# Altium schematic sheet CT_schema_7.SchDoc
size 405 x 379 mm
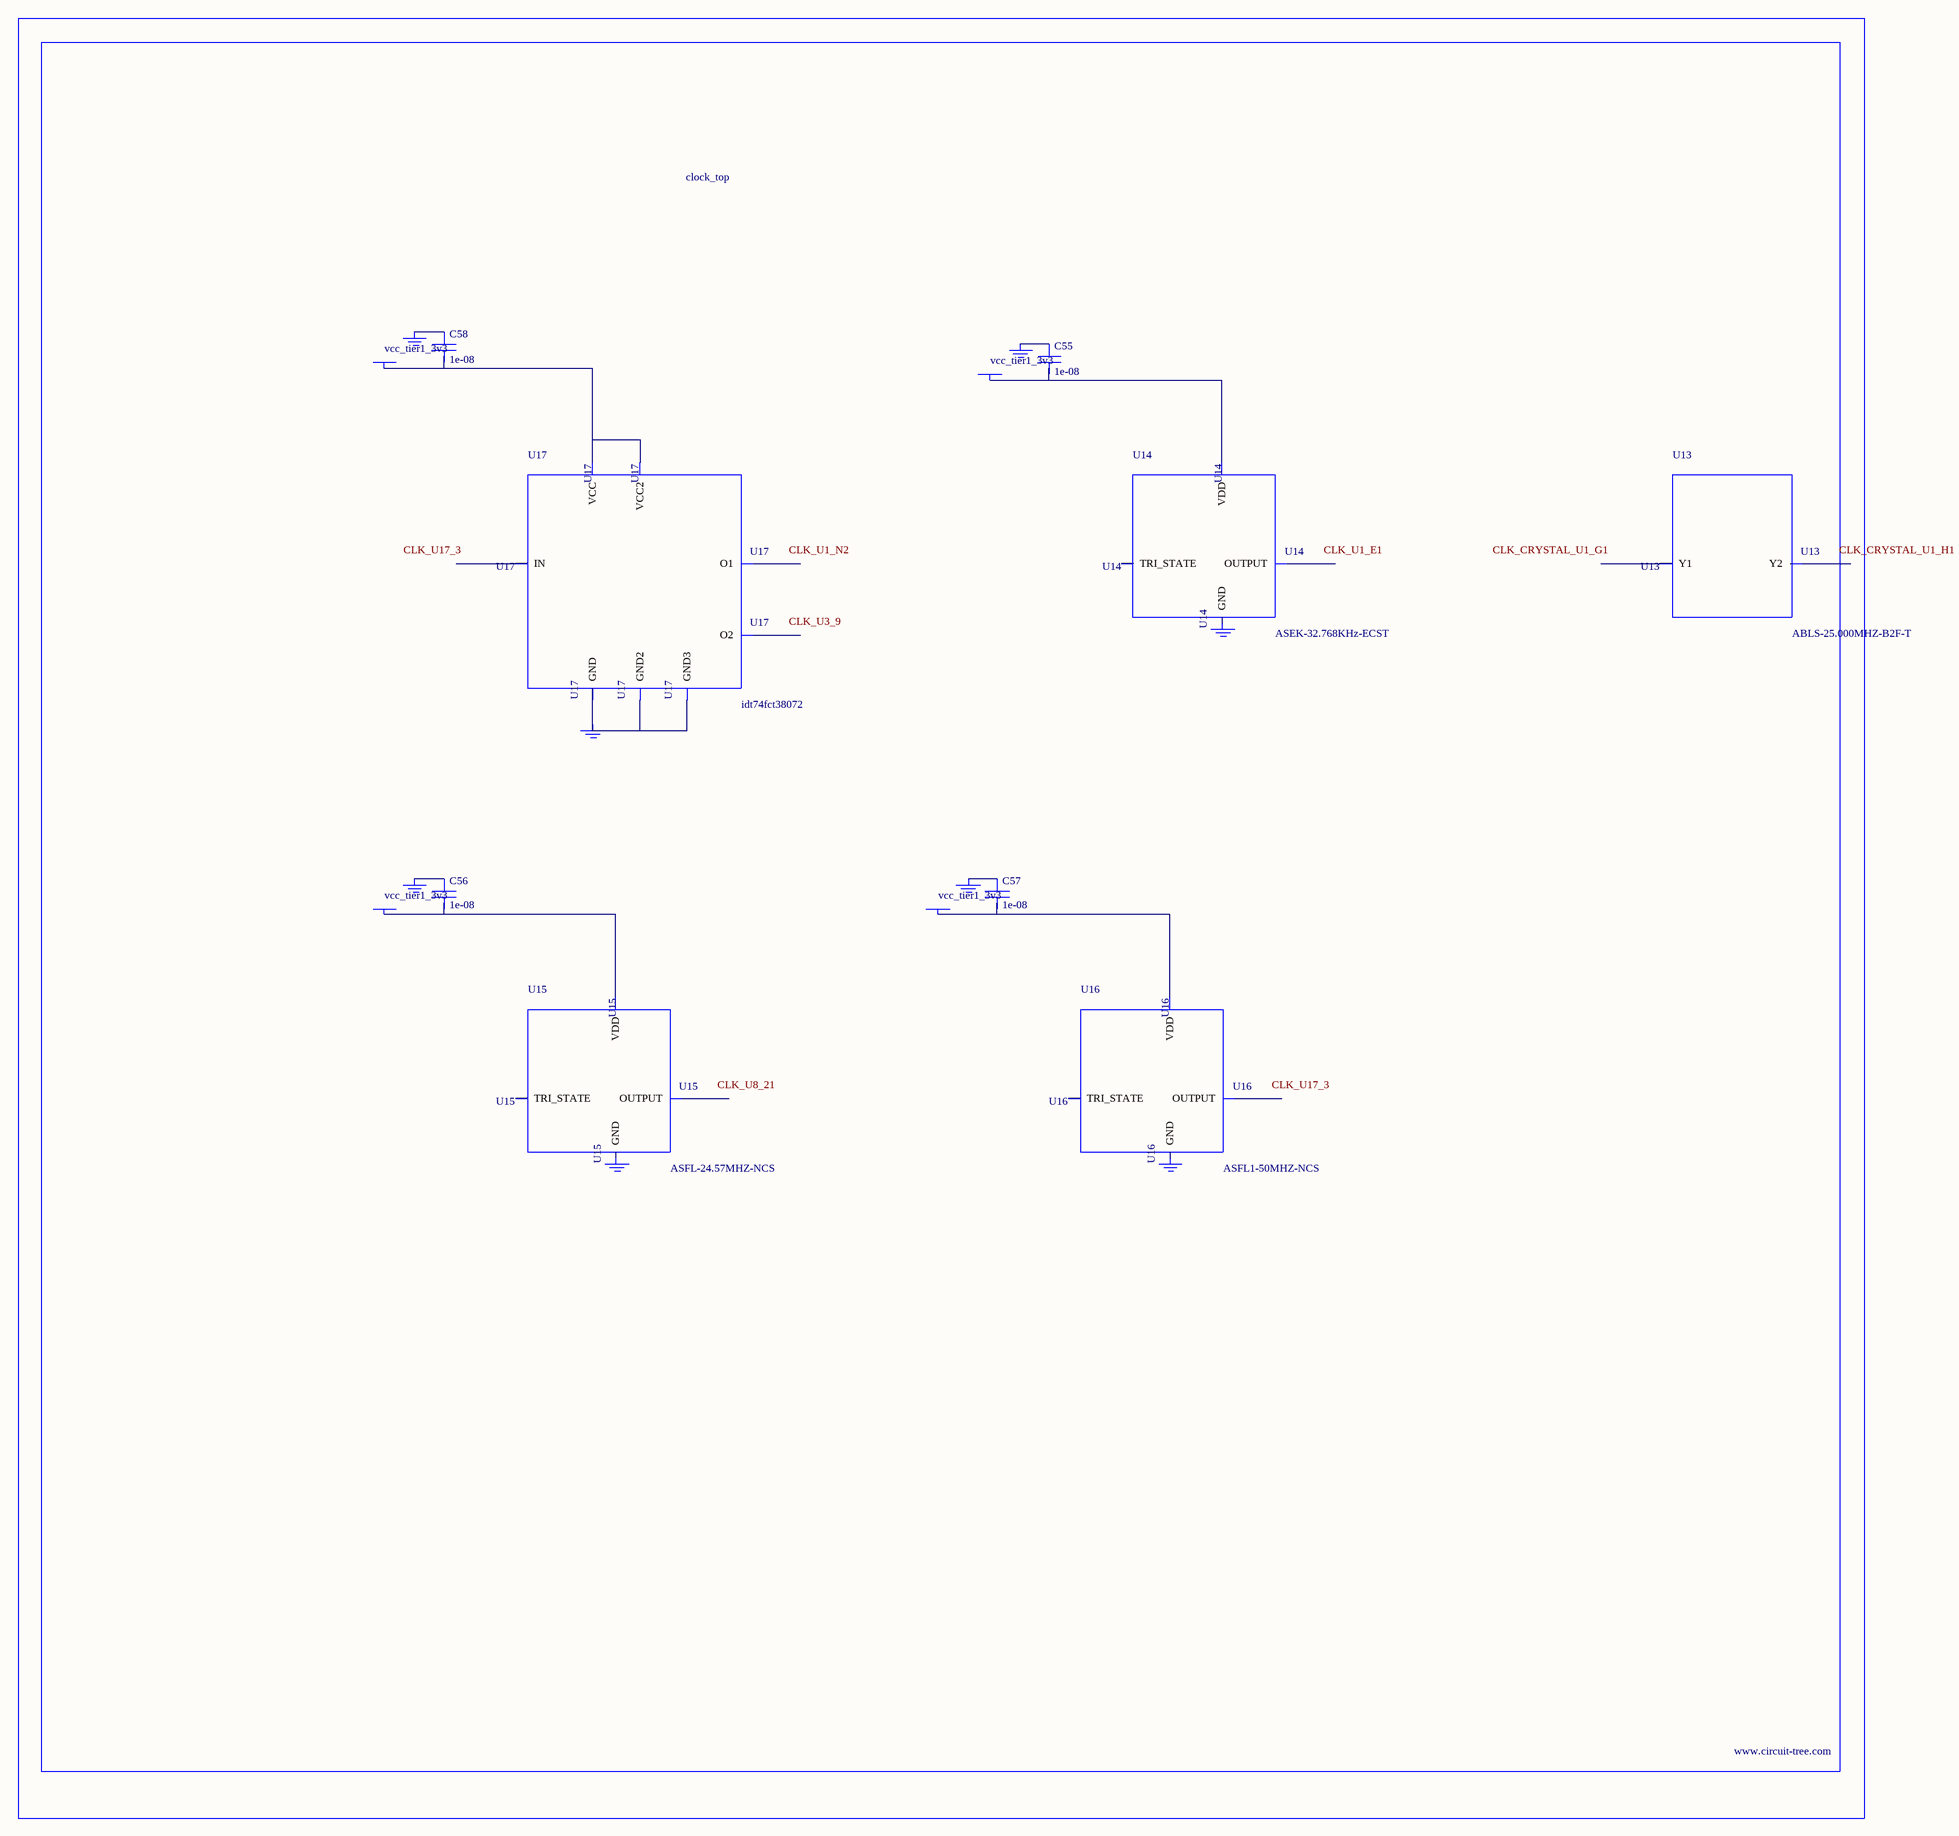
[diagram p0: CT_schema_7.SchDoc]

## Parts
BORDER6  (no value)
C55  1e-08  [C0402]
C56  1e-08  [C0402]
C57  1e-08  [C0402]
C58  1e-08  [C0402]
GND_INSTANCE_6_0  (no value)
GND_INSTANCE_6_1  (no value)
GND_INSTANCE_6_2  (no value)
GND_INSTANCE_6_3  (no value)
GND_INSTANCE_6_4  (no value)
GND_INSTANCE_6_5  (no value)
GND_INSTANCE_6_6  (no value)
GND_INSTANCE_6_7  (no value)
POWER_INSTANCE_6_0  vcc_tier1_3v3
POWER_INSTANCE_6_1  vcc_tier1_3v3
POWER_INSTANCE_6_2  vcc_tier1_3v3
POWER_INSTANCE_6_3  vcc_tier1_3v3
U13  ABLS-25.000MHZ-B2F-T  [ABLS-25.000MHZ-B2F-T]
U14  ASEK-32.768KHz-ECST  [ASEK]
U15  ASFL-24.57MHZ-NCS  [ASFL1]
U16  ASFL1-50MHZ-NCS  [ASFL1]
U17  idt74fct38072  [IDT74FCT38072]

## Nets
NetC55_1: C55.1 GND_INSTANCE_6_0.0(GND)
NetC55_2: C55.2 POWER_INSTANCE_6_0.0(PWR) U14.4(VDD)
NetC56_1: C56.1 GND_INSTANCE_6_2.0(GND)
NetC56_2: C56.2 POWER_INSTANCE_6_1.0(PWR) U15.4(VDD)
NetC57_1: C57.1 GND_INSTANCE_6_4.0(GND)
NetC57_2: C57.2 POWER_INSTANCE_6_2.0(PWR) U16.4(VDD)
NetC58_1: C58.1 GND_INSTANCE_6_6.0(GND)
NetC58_2: C58.2 POWER_INSTANCE_6_3.0(PWR) U17.1(VCC) U17.2(VCC2)
NetGND_INSTANCE_6_7_0: GND_INSTANCE_6_7.0(GND) U17.4(GND) U17.5(GND2) U17.8(GND3)

Not connected (* = marked no-connect by the designer): GND_INSTANCE_6_1 0(GND); GND_INSTANCE_6_3 0(GND); GND_INSTANCE_6_5 0(GND); U13 1(Y1) 2(Y2); U14 1(TRI_STATE) 2(GND) 3(OUTPUT); U15 1(TRI_STATE) 2(GND) 3(OUTPUT); U16 1(TRI_STATE) 2(GND) 3(OUTPUT); U17 3(IN) 6(O2) 7(O1)

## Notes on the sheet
- Labels drawn without touching a wire or pin: CLK_CRYSTAL_U1_G1, CLK_CRYSTAL_U1_H1, CLK_U1_E1, CLK_U1_N2, CLK_U3_9, CLK_U8_21, CLK_U17_3

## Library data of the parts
BORDER6 = BORDER_PAGE6
C55-C58 = C0402C103K3RAC
GND_INSTANCE_6_0-GND_INSTANCE_6_7 = GND
POWER_INSTANCE_6_0-POWER_INSTANCE_6_3 = PWR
